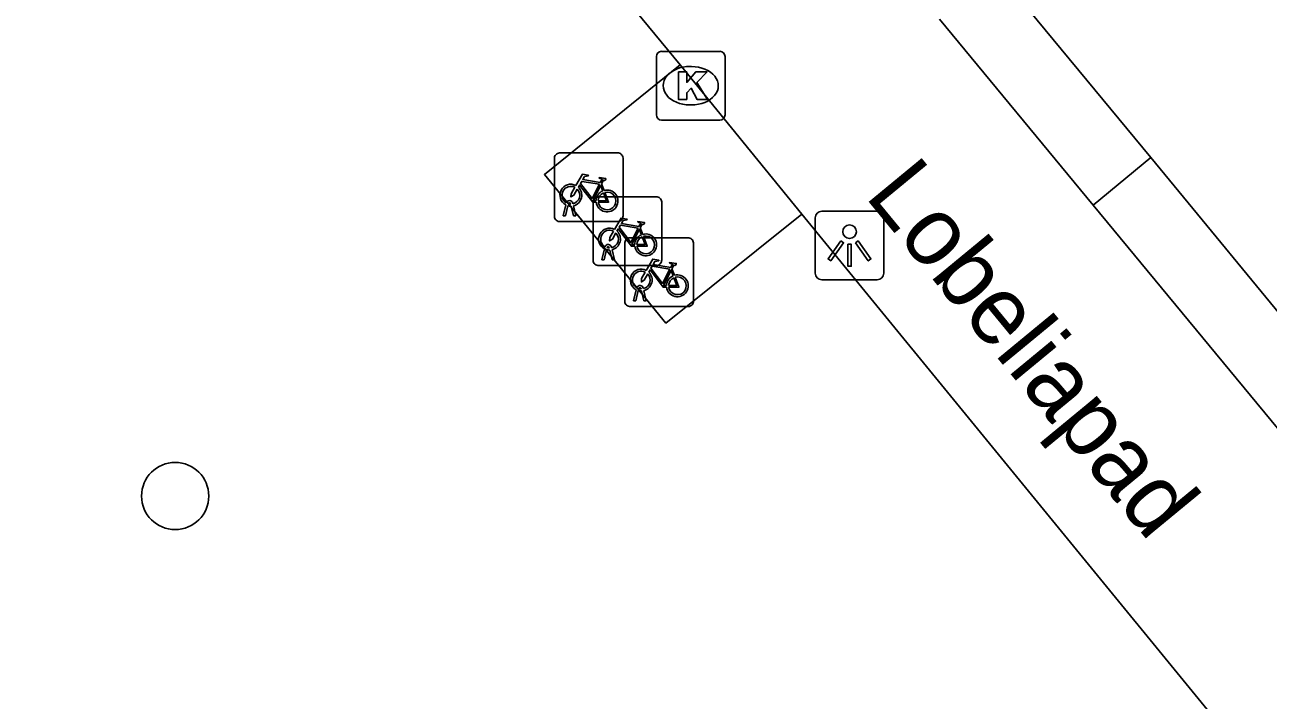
# Model space of a CAD drawing. Extents: x 162347 to 162868, y 381221 to 381813.
# Drawn here: x 162452 to 162470.1, y 381719.03 to 381728.86 of the extents above; entities that cross this region are included whole.
import ezdxf

# ---------------------------------------------------------------- set-up
doc = ezdxf.new("R2010")
doc.units = 0
for name, color, linetype in [('IMGEO_Boom', 7, 'Continuous'), ('IMGEO_Fietsenrek', 7, 'Continuous'), ('IMGEO_Kolk', 7, 'Continuous'), ('IMGEO_Lichtpunt', 7, 'Continuous'), ('IMGEO_Openbare_ruimte_label', 7, 'Continuous'), ('IMGEO_Pand', 7, 'Continuous'), ('IMGEO_Voetpad_open', 7, 'Continuous')]:
    doc.layers.add(name, color=color, linetype=linetype)

msp = doc.modelspace()

# ---------------------------------------------------------------- linework, layer by layer
at = {"layer": 'IMGEO_Boom'}
msp.add_circle((162454.185, 381722.001), 0.489, dxfattribs=at)
at = {"layer": 'IMGEO_Fietsenrek'}
for p, q in [((162459.708, 381726.069), (162459.708, 381726.91)), ((162459.708, 381726.91), (162459.708, 381726.069)), ((162459.783, 381726.994), (162460.624, 381726.994)), ((162460.624, 381726.994), (162459.783, 381726.994)), ((162460.708, 381726.919), (162460.708, 381726.078)), ((162460.708, 381726.078), (162460.708, 381726.919)), ((162460.395, 381726.543), (162460.431, 381726.448)), ((162460.346, 381726.355), (162461.187, 381726.355)), ((162461.187, 381726.355), (162460.346, 381726.355)), ((162459.835, 381726.078), (162459.874, 381726.238)), ((162459.904, 381726.226), (162459.869, 381726.078)), ((162459.946, 381726.25), (162459.945, 381726.254)), ((162459.987, 381726.078), (162459.953, 381726.22)), ((162459.977, 381726.261), (162459.978, 381726.254)), ((162459.985, 381726.224), (162460.02, 381726.078)), ((162460.271, 381725.43), (162460.271, 381726.271)), ((162460.271, 381726.271), (162460.271, 381725.43)), ((162461.271, 381726.28), (162461.271, 381725.439)), ((162461.271, 381725.439), (162461.271, 381726.28)), ((162460.633, 381725.994), (162459.792, 381725.994)), ((162459.792, 381725.994), (162460.633, 381725.994)), ((162459.869, 381726.078), (162459.835, 381726.078)), ((162460.02, 381726.078), (162459.987, 381726.078)), ((162460.958, 381725.904), (162460.994, 381725.809)), ((162460.733, 381724.834), (162460.733, 381725.675)), ((162460.733, 381725.675), (162460.733, 381724.834)), ((162460.808, 381725.759), (162461.649, 381725.759)), ((162461.649, 381725.759), (162460.808, 381725.759)), ((162461.733, 381725.684), (162461.733, 381724.843)), ((162461.733, 381724.843), (162461.733, 381725.684)), ((162460.398, 381725.439), (162460.437, 381725.599)), ((162460.467, 381725.587), (162460.432, 381725.439)), ((162460.509, 381725.611), (162460.508, 381725.615)), ((162460.55, 381725.439), (162460.516, 381725.581)), ((162460.54, 381725.622), (162460.541, 381725.615)), ((162460.548, 381725.585), (162460.583, 381725.439)), ((162461.196, 381725.355), (162460.355, 381725.355)), ((162460.355, 381725.355), (162461.196, 381725.355)), ((162460.432, 381725.439), (162460.398, 381725.439)), ((162460.583, 381725.439), (162460.55, 381725.439)), ((162461.42, 381725.308), (162461.456, 381725.213)), ((162460.86, 381724.843), (162460.899, 381725.003)), ((162460.929, 381724.991), (162460.894, 381724.843)), ((162460.971, 381725.015), (162460.97, 381725.019)), ((162461.012, 381724.843), (162460.978, 381724.985)), ((162461.002, 381725.026), (162461.003, 381725.019)), ((162461.01, 381724.989), (162461.045, 381724.843)), ((162461.658, 381724.759), (162460.817, 381724.759)), ((162460.817, 381724.759), (162461.658, 381724.759)), ((162460.894, 381724.843), (162460.86, 381724.843)), ((162461.045, 381724.843), (162461.012, 381724.843))]:
    msp.add_line(p, q, dxfattribs=at)
for points in [[(162460.021, 381726.52), (162460.116, 381726.684), (162460.202, 381726.67), (162460.204, 381726.661), (162460.148, 381726.65), (162460.121, 381726.605), (162460.377, 381726.564)], [(162460.364, 381726.539), (162460.107, 381726.58), (162460.09, 381726.551), (162460.257, 381726.331), (162460.364, 381726.539)], [(162460.377, 381726.564), (162460.402, 381726.613), (162460.396, 381726.617), (162460.373, 381726.621), (162460.361, 381726.628), (162460.36, 381726.631), (162460.362, 381726.636), (162460.457, 381726.621), (162460.459, 381726.611), (162460.449, 381726.598), (162460.437, 381726.592), (162460.423, 381726.598), (162460.395, 381726.543)], [(162460.042, 381726.468), (162459.99, 381726.378), (162459.95, 381726.353), (162459.951, 381726.4), (162460.006, 381726.494)], [(162460.317, 381726.276), (162460.267, 381726.276), (162460.076, 381726.527), (162460.057, 381726.495)], [(162460.412, 381726.441), (162460.382, 381726.518), (162460.273, 381726.3), (162460.316, 381726.3)], [(162460.346, 381726.3), (162460.466, 381726.299), (162460.422, 381726.413)], [(162460.442, 381726.42), (162460.497, 381726.275), (162460.347, 381726.275)], [(162460.584, 381725.881), (162460.679, 381726.045), (162460.765, 381726.031), (162460.767, 381726.022), (162460.711, 381726.011), (162460.684, 381725.966), (162460.94, 381725.925)], [(162460.94, 381725.925), (162460.965, 381725.974), (162460.959, 381725.978), (162460.936, 381725.982), (162460.924, 381725.989), (162460.923, 381725.992), (162460.925, 381725.997), (162461.02, 381725.982), (162461.022, 381725.972), (162461.012, 381725.959), (162461, 381725.953), (162460.986, 381725.959), (162460.958, 381725.904)], [(162460.605, 381725.829), (162460.553, 381725.739), (162460.513, 381725.714), (162460.514, 381725.761), (162460.569, 381725.855)], [(162460.88, 381725.637), (162460.83, 381725.637), (162460.639, 381725.888), (162460.62, 381725.856)], [(162460.927, 381725.9), (162460.67, 381725.941), (162460.653, 381725.912), (162460.82, 381725.692), (162460.927, 381725.9)], [(162460.975, 381725.802), (162460.945, 381725.879), (162460.836, 381725.661), (162460.879, 381725.661)], [(162460.909, 381725.661), (162461.029, 381725.66), (162460.985, 381725.774)], [(162461.005, 381725.781), (162461.06, 381725.636), (162460.91, 381725.636)], [(162461.046, 381725.285), (162461.141, 381725.449), (162461.227, 381725.435), (162461.229, 381725.426), (162461.173, 381725.415), (162461.146, 381725.37), (162461.402, 381725.329)], [(162461.342, 381725.041), (162461.292, 381725.041), (162461.101, 381725.292), (162461.082, 381725.26)], [(162461.389, 381725.304), (162461.132, 381725.345), (162461.115, 381725.316), (162461.282, 381725.096), (162461.389, 381725.304)], [(162461.437, 381725.206), (162461.407, 381725.283), (162461.298, 381725.065), (162461.341, 381725.065)], [(162461.402, 381725.329), (162461.427, 381725.378), (162461.421, 381725.382), (162461.398, 381725.386), (162461.386, 381725.393), (162461.385, 381725.396), (162461.387, 381725.401), (162461.482, 381725.386), (162461.484, 381725.376), (162461.474, 381725.363), (162461.462, 381725.357), (162461.448, 381725.363), (162461.42, 381725.308)], [(162461.067, 381725.233), (162461.015, 381725.143), (162460.975, 381725.118), (162460.976, 381725.165), (162461.031, 381725.259)], [(162461.371, 381725.065), (162461.491, 381725.064), (162461.447, 381725.178)], [(162461.467, 381725.185), (162461.522, 381725.04), (162461.372, 381725.04)]]:
    msp.add_lwpolyline(points, dxfattribs=at)
for centre, radius, start, end in [((162459.786, 381726.916), 0.0779, 92.4484, 184.2845), ((162459.786, 381726.916), 0.0779, 92.4484, 184.2845), ((162460.63, 381726.916), 0.0779, 2.4484, 94.2845), ((162460.63, 381726.916), 0.0779, 2.4484, 94.2845), ((162459.948, 381726.379), 0.159, 62.6766, 242.1369), ((162459.948, 381726.379), 0.129, 63.3192, 238.903), ((162459.948, 381726.379), 0.129, 283.6043, 43.4302), ((162459.948, 381726.379), 0.159, 283.5766, 46.6042), ((162460.349, 381726.277), 0.0779, 92.4484, 184.2845), ((162460.349, 381726.277), 0.0779, 92.4484, 184.2845), ((162460.475, 381726.295), 0.159, 113.3408, 178.3217), ((162460.475, 381726.295), 0.159, 187.0065, 105.7708), ((162460.475, 381726.295), 0.129, 113.923, 177.9556), ((162460.475, 381726.295), 0.129, 188.6715, 104.5883), ((162461.193, 381726.277), 0.0779, 2.4484, 94.2845), ((162461.193, 381726.277), 0.0779, 2.4484, 94.2845), ((162459.928, 381726.25), 0.0499, 12.8025, 158.6934), ((162459.948, 381726.379), 0.159, 253.9967, 271.7867), ((162459.928, 381726.25), 0.0174, 12.8025, 163.4502), ((162459.948, 381726.379), 0.129, 253.415, 269.0204), ((162459.786, 381726.072), 0.0779, 182.4484, 274.2845), ((162459.786, 381726.072), 0.0779, 182.4484, 274.2845), ((162460.63, 381726.072), 0.0779, 272.4484, 4.2845), ((162460.63, 381726.072), 0.0779, 272.4484, 4.2845), ((162460.511, 381725.74), 0.159, 62.6766, 242.1369), ((162460.511, 381725.74), 0.129, 63.3192, 238.903), ((162460.511, 381725.74), 0.129, 283.6043, 43.4302), ((162460.511, 381725.74), 0.159, 283.5766, 46.6042), ((162461.038, 381725.656), 0.159, 187.0065, 105.7708), ((162460.491, 381725.611), 0.0499, 12.8025, 158.6934), ((162460.811, 381725.681), 0.0779, 92.4484, 184.2845), ((162460.811, 381725.681), 0.0779, 92.4484, 184.2845), ((162461.038, 381725.656), 0.159, 113.3408, 178.3217), ((162461.038, 381725.656), 0.129, 113.923, 177.9556), ((162461.038, 381725.656), 0.129, 188.6715, 104.5883), ((162461.655, 381725.681), 0.0779, 2.4484, 94.2845), ((162461.655, 381725.681), 0.0779, 2.4484, 94.2845), ((162460.511, 381725.74), 0.159, 253.9967, 271.7867), ((162460.491, 381725.611), 0.0174, 12.8025, 163.4502), ((162460.511, 381725.74), 0.129, 253.415, 269.0204), ((162460.349, 381725.433), 0.0779, 182.4484, 274.2845), ((162460.349, 381725.433), 0.0779, 182.4484, 274.2845), ((162460.973, 381725.144), 0.159, 62.6766, 242.1369), ((162460.973, 381725.144), 0.129, 63.3192, 238.903), ((162461.193, 381725.433), 0.0779, 272.4484, 4.2845), ((162461.193, 381725.433), 0.0779, 272.4484, 4.2845), ((162460.973, 381725.144), 0.129, 283.6043, 43.4302), ((162460.973, 381725.144), 0.159, 283.5766, 46.6042), ((162461.5, 381725.06), 0.159, 113.3408, 178.3217), ((162461.5, 381725.06), 0.159, 187.0065, 105.7708), ((162461.5, 381725.06), 0.129, 113.923, 177.9556), ((162461.5, 381725.06), 0.129, 188.6715, 104.5883), ((162460.953, 381725.015), 0.0499, 12.8025, 158.6934), ((162460.973, 381725.144), 0.159, 253.9967, 271.7867), ((162460.953, 381725.015), 0.0174, 12.8025, 163.4502), ((162460.973, 381725.144), 0.129, 253.415, 269.0204), ((162460.811, 381724.837), 0.0779, 182.4484, 274.2845), ((162460.811, 381724.837), 0.0779, 182.4484, 274.2845), ((162461.655, 381724.837), 0.0779, 272.4484, 4.2845), ((162461.655, 381724.837), 0.0779, 272.4484, 4.2845)]:
    msp.add_arc(centre, radius, start, end, dxfattribs=at)
at = {"layer": 'IMGEO_Kolk'}
for p, q in [((162461.193, 381727.546), (162461.193, 381728.398)), ((162461.268, 381728.472), (162462.12, 381728.472)), ((162462.194, 381728.398), (162462.194, 381727.546)), ((162461.681, 381728.252), (162461.706, 381728.252)), ((162461.704, 381727.692), (162461.679, 381727.692)), ((162462.12, 381727.472), (162461.268, 381727.472))]:
    msp.add_line(p, q, dxfattribs=at)
for points in [[(162461.193, 381727.546), (162461.193, 381728.398)], [(162461.268, 381728.472), (162462.12, 381728.472)], [(162462.194, 381728.398), (162462.194, 381727.546)], [(162461.514, 381728.172), (162461.637, 381728.172), (162461.637, 381728.021), (162461.767, 381728.172), (162461.931, 381728.172), (162461.785, 381728.021), (162461.938, 381727.772), (162461.786, 381727.772), (162461.701, 381727.936), (162461.637, 381727.869), (162461.637, 381727.772), (162461.514, 381727.772), (162461.514, 381728.172)], [(162462.12, 381727.472), (162461.268, 381727.472)]]:
    msp.add_lwpolyline(points, dxfattribs=at)
for centre, start, end in [((162461.27, 381728.396), 91.552, 178.448), ((162461.27, 381728.396), 91.552, 178.448), ((162462.118, 381728.396), 1.552, 88.448), ((162462.118, 381728.396), 1.552, 88.448), ((162461.27, 381727.548), 181.552, 268.448), ((162461.27, 381727.548), 181.552, 268.448), ((162462.118, 381727.548), 271.552, 358.448), ((162462.118, 381727.548), 271.552, 358.448)]:
    msp.add_arc(centre, 0.0765, start, end, dxfattribs=at)
for centre, major_axis, ratio, start_param, end_param in [((162461.68, 381727.972), (-0.387, 0.002), 0.722429, 4.712389, 7.853982), ((162461.705, 381727.972), (-0.39, 0.002), 0.717154, 1.570796, 4.712389)]:
    msp.add_ellipse(centre, major_axis=major_axis, ratio=ratio, start_param=start_param, end_param=end_param, dxfattribs=at)
at = {"layer": 'IMGEO_Lichtpunt'}
for p, q in [((162463.508, 381726.05), (162463.508, 381725.243)), ((162463.508, 381726.05), (162463.508, 381725.243)), ((162464.41, 381726.145), (162463.602, 381726.145)), ((162464.41, 381726.145), (162463.602, 381726.145)), ((162464.504, 381725.243), (162464.504, 381726.05)), ((162464.504, 381725.243), (162464.504, 381726.05)), ((162463.602, 381725.149), (162464.41, 381725.149)), ((162463.602, 381725.149), (162464.41, 381725.149))]:
    msp.add_line(p, q, dxfattribs=at)
for points in [[(162463.882, 381725.714), (162463.921, 381725.686), (162463.733, 381725.424), (162463.695, 381725.451), (162463.882, 381725.714)], [(162463.984, 381725.666), (162464.031, 381725.666), (162464.031, 381725.344), (162463.984, 381725.344), (162463.984, 381725.666)], [(162464.094, 381725.686), (162464.132, 381725.713), (162464.319, 381725.451), (162464.28, 381725.423), (162464.094, 381725.686)]]:
    msp.add_lwpolyline(points, dxfattribs=at)
msp.add_circle((162464.007, 381725.848), 0.0994, dxfattribs=at)
for centre, start, end in [((162463.602, 381726.05), 90, 180), ((162463.602, 381726.05), 90, 180), ((162464.41, 381726.05), 0, 90), ((162464.41, 381726.05), 0, 90), ((162463.602, 381725.243), 180, 270), ((162463.602, 381725.243), 180, 270), ((162464.41, 381725.243), 270, 0), ((162464.41, 381725.243), 270, 360)]:
    msp.add_arc(centre, 0.0946, start, end, dxfattribs=at)
at = {"layer": 'IMGEO_Pand'}
for points in [[(162468.393, 381726.927), (162466.159, 381729.634)], [(162472.969, 381721.38), (162468.393, 381726.927)]]:
    msp.add_lwpolyline(points, dxfattribs=at)
at = {"layer": 'IMGEO_Voetpad_open'}
for points in [[(162451.996, 381739.827), (162461.541, 381728.274)], [(162465.316, 381728.939), (162467.553, 381726.234)], [(162463.314, 381726.102), (162461.333, 381724.518), (162459.563, 381726.678), (162461.541, 381728.274)], [(162461.541, 381728.274), (162463.314, 381726.102)], [(162468.393, 381726.927), (162467.553, 381726.234)], [(162467.553, 381726.234), (162472.137, 381720.694)], [(162463.314, 381726.102), (162469.783, 381718.202)]]:
    msp.add_lwpolyline(points, dxfattribs=at)

# ---------------------------------------------------------------- texts
at = {"layer": 'IMGEO_Openbare_ruimte_label'}
msp.add_text('Lobeliapad', height=1, rotation=309.4829, dxfattribs=at).set_placement((162464.216, 381726.367))

doc.saveas('drawing.dxf')
